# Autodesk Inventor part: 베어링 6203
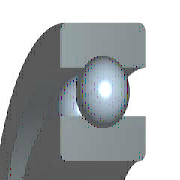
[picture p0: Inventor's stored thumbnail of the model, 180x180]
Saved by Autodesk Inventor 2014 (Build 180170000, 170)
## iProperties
IsCustomPart: 0
Company: 한국ATC센터
Created: 2014-08
Part Number: 베어링 6203
Material: 강, 연강
Description: 깊은 그루브 볼 베어링
Document SubType Name: Modeling
Standard: KS B 2023
Designer: KYOUNG IL JANG
Standards Organization: KS
Language: ko-KR
Size Designation: 6203 - 17 x 40 x 12
Categories: <MemberInstance><Categories><Category DisplayName="샤프트 부품" InternalName="7f7aeb1f-a693-4053-b835-cee3144e0d98" Mnemonic="SHFT"><Category DisplayName="베어링" Inter
Density: 1 g/cm^3
Appearance: 크롬 - 광택
Author: KYOUNG IL JANG
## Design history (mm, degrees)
sketch "스케치" dims "d0" = 5.98 (= -0.26 x WD + 0.26 x BD)
  geometry: L1 (3.01, 14.25)-(8.99, 14.25); L2 (6, 14.25)-(6, 11.26); L3 (6, 14.25)-(6, 17.24); L4 (3.778, 12.249)-(0, 12.249); L5 (0, 8.5)-(12, 8.5); L6 (3.778, 16.251)-(0, 16.251); L7 (0, 20)-(12, 20); L8 (12, 8.5)-(12, 12.249); L9 (8.222, 12.249)-(12, 12.249); L10 (8.222, 16.251)-(12, 16.251); L11 (12, 20)-(12, 16.251); L12 (-1.4, 0)-(8.4, 0) reference; L13 (0, -0.3)-(0, 5.3) reference
  constraints: 22 end point, 4 point on line, 2 collinear, 2 perpendicular, 2 symmetric about line, 1 midpoint, 1 parallel, 14 other
  dimensions: "d9" = 17 diameter of L5 L12 (= WD); "d11" = 40 diameter of L7 L12 (= BD); "d12" = 12 distance between parallel lines of L8 L13 (= KB); "d13" = 24.498 diameter of L9 L12 (= 0.326 x BD + 0.674 x WD)
revolve "본체" stored, may be unused: angle "d6" = 90 deg
revolve "볼" stored, may be unused: angle "d7" = 90 deg
pattern_circular "IDS_ARRAYBALL[SIMPL:T]" dims angle "d3" = 360 deg
body "Solid1"
fillet "모깎기1" dims "d1" = 0.6 (= KRS)
other parameters: "WD" = 17 [user parameter; used in 5 equation terms], "BD" = 40 [user parameter; used in 5 equation terms], "KB" = 12 [user parameter; used in 1 equation term], "KRS" = 0.6 [user parameter; used in 1 equation term], "d4" = 0, "d5" = 0, "d8" = 0, "d14" = 0, "d15" = 0, "BBA" = 0 [user parameter], "BC0" = 4750000 [user parameter], "BC" = 9560000 [user parameter], "WR" = 8.5 (= 0.5 x WD) [user parameter]
